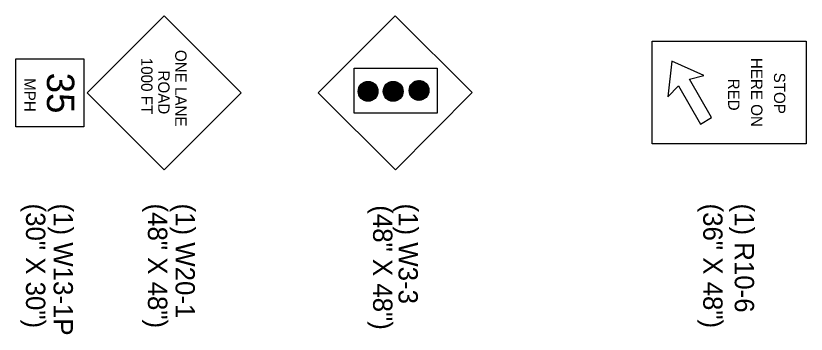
# Model space of a CAD drawing. Extents: x 1678017 to 1687792, y 404433 to 413488.
# Drawn here: x 1680249.4 to 1680494.8, y 405048.9 to 405147.8 of the extents above; entities that cross this region are included whole.
import ezdxf

# ---------------------------------------------------------------- set-up
doc = ezdxf.new("R2010")
doc.units = 0
doc.layers.add('Default', color=7, linetype='Continuous')

msp = doc.modelspace()

# ---------------------------------------------------------------- linework, layer by layer
at = {"layer": 'Default'}
for p, q in [((1680271.55, 405123.92), (1680295.44, 405147.83)), ((1680319.34, 405123.92), (1680295.44, 405147.83)), ((1680343.27, 405123.88), (1680367.13, 405147.83)), ((1680391.05, 405123.96), (1680367.13, 405147.83)), ((1680356.65, 405126.64), (1680361.01, 405122.28)), ((1680356.75, 405126.72), (1680361.1, 405122.38)), ((1680356.86, 405126.81), (1680361.18, 405122.48)), ((1680356.97, 405126.89), (1680361.26, 405122.59)), ((1680357.08, 405126.96), (1680361.34, 405122.71)), ((1680357.2, 405127.04), (1680361.41, 405122.83)), ((1680357.32, 405127.1), (1680361.48, 405122.95)), ((1680357.45, 405127.16), (1680361.54, 405123.08)), ((1680357.58, 405127.22), (1680361.59, 405123.21)), ((1680357.72, 405127.27), (1680361.65, 405123.35)), ((1680357.87, 405127.32), (1680361.69, 405123.49)), ((1680358.02, 405127.36), (1680361.73, 405123.64)), ((1680358.17, 405127.39), (1680361.76, 405123.8)), ((1680358.34, 405127.42), (1680361.79, 405123.96)), ((1680358.51, 405127.43), (1680361.81, 405124.14)), ((1680358.69, 405127.44), (1680361.81, 405124.32)), ((1680358.88, 405127.44), (1680361.81, 405124.51)), ((1680359.09, 405127.42), (1680361.79, 405124.72)), ((1680359.32, 405127.39), (1680361.76, 405124.94)), ((1680359.56, 405127.33), (1680361.7, 405125.19)), ((1680359.85, 405127.23), (1680361.6, 405125.48)), ((1680360.2, 405127.07), (1680361.44, 405125.83)), ((1680364.5, 405126.68), (1680368.85, 405122.32)), ((1680364.6, 405126.76), (1680368.94, 405122.43)), ((1680364.71, 405126.84), (1680369.02, 405122.53)), ((1680364.82, 405126.92), (1680369.1, 405122.64)), ((1680364.93, 405127), (1680369.17, 405122.76)), ((1680365.05, 405127.07), (1680369.24, 405122.88)), ((1680365.18, 405127.13), (1680369.3, 405123.01)), ((1680365.31, 405127.19), (1680369.36, 405123.14)), ((1680365.44, 405127.24), (1680369.42, 405123.27)), ((1680365.59, 405127.29), (1680369.47, 405123.41)), ((1680365.73, 405127.34), (1680369.51, 405123.56)), ((1680365.88, 405127.37), (1680369.55, 405123.71)), ((1680366.04, 405127.4), (1680369.58, 405123.87)), ((1680366.21, 405127.43), (1680369.6, 405124.04)), ((1680366.39, 405127.44), (1680369.61, 405124.22)), ((1680366.58, 405127.44), (1680369.62, 405124.4)), ((1680366.77, 405127.43), (1680369.61, 405124.6)), ((1680366.99, 405127.41), (1680369.58, 405124.82)), ((1680367.22, 405127.36), (1680369.54, 405125.05)), ((1680367.49, 405127.29), (1680369.46, 405125.31)), ((1680367.79, 405127.17), (1680369.35, 405125.62)), ((1680368.21, 405126.94), (1680369.12, 405126.04)), ((1680372.24, 405126.67), (1680376.6, 405122.32)), ((1680372.33, 405126.77), (1680376.7, 405122.41)), ((1680372.43, 405126.87), (1680376.79, 405122.51)), ((1680372.53, 405126.96), (1680376.88, 405122.6)), ((1680372.63, 405127.04), (1680376.97, 405122.71)), ((1680372.74, 405127.13), (1680377.05, 405122.82)), ((1680372.85, 405127.21), (1680377.13, 405122.93)), ((1680372.97, 405127.28), (1680377.2, 405123.04)), ((1680373.09, 405127.35), (1680377.27, 405123.16)), ((1680373.21, 405127.41), (1680377.34, 405123.29)), ((1680373.34, 405127.47), (1680377.4, 405123.42)), ((1680373.48, 405127.53), (1680377.45, 405123.55)), ((1680373.62, 405127.58), (1680377.5, 405123.69)), ((1680373.76, 405127.62), (1680377.54, 405123.84)), ((1680373.92, 405127.66), (1680377.58, 405123.99)), ((1680374.08, 405127.69), (1680377.61, 405124.15)), ((1680374.24, 405127.71), (1680377.63, 405124.32)), ((1680374.42, 405127.72), (1680377.64, 405124.5)), ((1680374.61, 405127.72), (1680377.65, 405124.68)), ((1680374.81, 405127.72), (1680377.64, 405124.88)), ((1680375.02, 405127.69), (1680377.61, 405125.1)), ((1680375.25, 405127.65), (1680377.57, 405125.33)), ((1680375.52, 405127.57), (1680377.5, 405125.59)), ((1680375.83, 405127.45), (1680377.38, 405125.9)), ((1680376.24, 405127.23), (1680377.15, 405126.32)), ((1680355.65, 405124.6), (1680358.97, 405121.28)), ((1680355.65, 405124.42), (1680358.79, 405121.27)), ((1680355.65, 405124.22), (1680358.6, 405121.28)), ((1680355.67, 405124.77), (1680359.14, 405121.3)), ((1680355.7, 405124.93), (1680359.3, 405121.33)), ((1680355.73, 405125.09), (1680359.46, 405121.36)), ((1680355.77, 405125.24), (1680359.61, 405121.4)), ((1680355.82, 405125.38), (1680359.75, 405121.45)), ((1680355.93, 405125.65), (1680360.02, 405121.56)), ((1680355.99, 405125.78), (1680360.15, 405121.62)), ((1680356.06, 405125.9), (1680360.27, 405121.69)), ((1680356.13, 405126.02), (1680360.39, 405121.76)), ((1680356.21, 405126.13), (1680360.5, 405121.83)), ((1680356.29, 405126.24), (1680360.61, 405121.91)), ((1680356.37, 405126.35), (1680360.72, 405122)), ((1680356.46, 405126.45), (1680360.82, 405122.09)), ((1680356.55, 405126.54), (1680360.92, 405122.18)), ((1680363.45, 405124.5), (1680366.67, 405121.28)), ((1680363.45, 405124.31), (1680366.48, 405121.27)), ((1680363.46, 405124.67), (1680366.85, 405121.29)), ((1680363.48, 405124.84), (1680367.02, 405121.31)), ((1680363.51, 405125), (1680367.18, 405121.34)), ((1680363.55, 405125.16), (1680367.33, 405121.38)), ((1680363.59, 405125.3), (1680367.48, 405121.42)), ((1680363.64, 405125.44), (1680367.62, 405121.47)), ((1680363.7, 405125.58), (1680367.75, 405121.52)), ((1680363.76, 405125.71), (1680367.88, 405121.58)), ((1680363.82, 405125.83), (1680368.01, 405121.65)), ((1680363.89, 405125.95), (1680368.13, 405121.72)), ((1680363.96, 405126.07), (1680368.24, 405121.79)), ((1680364.04, 405126.18), (1680368.35, 405121.87)), ((1680364.13, 405126.29), (1680368.46, 405121.95)), ((1680364.21, 405126.39), (1680368.56, 405122.04)), ((1680364.3, 405126.49), (1680368.66, 405122.13)), ((1680364.4, 405126.59), (1680368.76, 405122.22)), ((1680371.48, 405124.78), (1680374.7, 405121.56)), ((1680371.48, 405124.59), (1680374.52, 405121.56)), ((1680371.49, 405124.96), (1680374.88, 405121.57)), ((1680371.49, 405124.39), (1680374.32, 405121.56)), ((1680371.51, 405124.18), (1680374.1, 405121.59)), ((1680371.52, 405125.12), (1680375.05, 405121.59)), ((1680371.55, 405125.28), (1680375.21, 405121.62)), ((1680371.58, 405125.44), (1680375.36, 405121.66)), ((1680371.63, 405125.58), (1680375.51, 405121.7)), ((1680371.68, 405125.72), (1680375.65, 405121.75)), ((1680371.73, 405125.86), (1680375.78, 405121.81)), ((1680371.79, 405125.99), (1680375.91, 405121.87)), ((1680371.85, 405126.12), (1680376.04, 405121.93)), ((1680371.92, 405126.24), (1680376.16, 405122)), ((1680372, 405126.35), (1680376.27, 405122.07)), ((1680372.07, 405126.46), (1680376.39, 405122.15)), ((1680372.16, 405126.57), (1680376.49, 405122.23)), ((1680295.44, 405100.02), (1680271.55, 405123.92)), ((1680295.44, 405100.02), (1680319.34, 405123.92)), ((1680367.21, 405100.02), (1680343.27, 405123.88)), ((1680355.66, 405124.02), (1680358.39, 405121.29)), ((1680355.7, 405123.8), (1680358.17, 405121.32)), ((1680355.75, 405123.55), (1680357.92, 405121.38)), ((1680355.84, 405123.27), (1680357.64, 405121.47)), ((1680356, 405122.93), (1680357.3, 405121.62)), ((1680356.41, 405122.33), (1680356.7, 405122.04)), ((1680363.46, 405124.11), (1680366.29, 405121.28)), ((1680363.48, 405123.9), (1680366.07, 405121.31)), ((1680363.53, 405123.66), (1680365.84, 405121.35)), ((1680363.6, 405123.4), (1680365.57, 405121.42)), ((1680363.72, 405123.09), (1680365.26, 405121.54)), ((1680363.95, 405122.67), (1680364.85, 405121.77)), ((1680367.21, 405100.02), (1680391.05, 405123.96)), ((1680371.56, 405123.95), (1680373.87, 405121.63)), ((1680371.63, 405123.68), (1680373.61, 405121.71)), ((1680371.75, 405123.37), (1680373.3, 405121.83)), ((1680371.98, 405122.96), (1680372.88, 405122.06))]:
    msp.add_line(p, q, dxfattribs=at)
for points in [[(1680494.76, 405108.03), (1680446.95, 405108.03), (1680446.95, 405139.9), (1680494.76, 405139.9)], [(1680270.48, 405134.49), (1680270.48, 405113.36), (1680249.36, 405113.36), (1680249.36, 405134.49)], [(1680380.18, 405131.54), (1680380.18, 405117.6), (1680354.45, 405117.6), (1680354.45, 405131.54)], [(1680465.32, 405116.18), (1680458.5, 405128.12), (1680462.97, 405129.31), (1680453.05, 405133.73), (1680451.84, 405122.64), (1680455.07, 405126.09), (1680461.93, 405114.19)]]:
    msp.add_lwpolyline(points, close=True, dxfattribs=at)
for centre in [(1680358.73, 405124.36), (1680366.53, 405124.36), (1680374.56, 405124.64)]:
    msp.add_circle(centre, 3.08, dxfattribs=at)

# ---------------------------------------------------------------- texts
for s, height, rotation, p in [('ONE LANE', 3.521, 270.0004, (1680298.84, 405137.22)), ('1000 FT', 3.522, 270.0006, (1680288.28, 405134.78)), ('HERE ON', 3.521, 270.0004, (1680477.65, 405134.76)), ('35', 8.51, 270, (1680259.02, 405130.15)), ('ROAD', 3.52, 270, (1680293.56, 405130.83)), ('STOP', 3.521, 270.0004, (1680484.76, 405130.16)), ('MPH', 3.522, 270.0006, (1680251.96, 405128.47)), ('RED', 3.521, 270.0004, (1680470.53, 405128.3)), ('(30" X 30")', 6, 270, (1680252.52, 405089.5)), ('(1) W13-1P', 6, 270, (1680261.09, 405089.5)), ('(48" X 48")', 6, 270, (1680290.39, 405089.5)), ('(1) W20-1', 6, 270, (1680298.95, 405089.5)), ('(48" X 48")', 6, 270, (1680360.29, 405088.97)), ('(1) W3-3', 6, 270, (1680368.19, 405089.5)), ('(36" X 48")', 6, 270, (1680462.79, 405089.5)), ('(1) R10-6', 6, 270, (1680472.57, 405089.5))]:
    msp.add_text(s, height=height, rotation=rotation, dxfattribs=at).set_placement(p)

doc.saveas('drawing.dxf')
